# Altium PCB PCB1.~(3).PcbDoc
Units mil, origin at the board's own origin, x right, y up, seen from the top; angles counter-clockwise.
Board outline 6000 x 4000 mil, 2 copper layers (Top Layer, Bottom Layer); 138 components, 71 nets, 353 pads, 0 vias.
Unrouted connection lines stored in the file: 264.
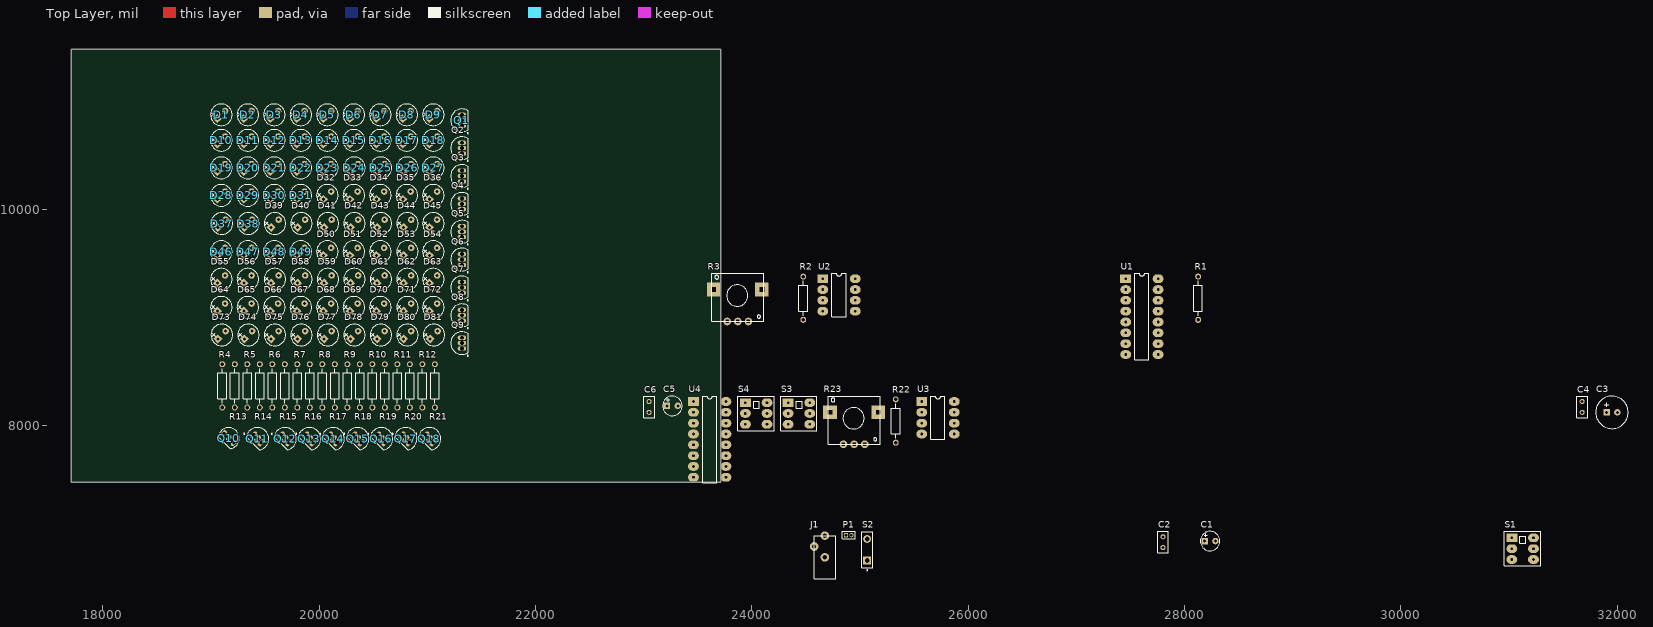
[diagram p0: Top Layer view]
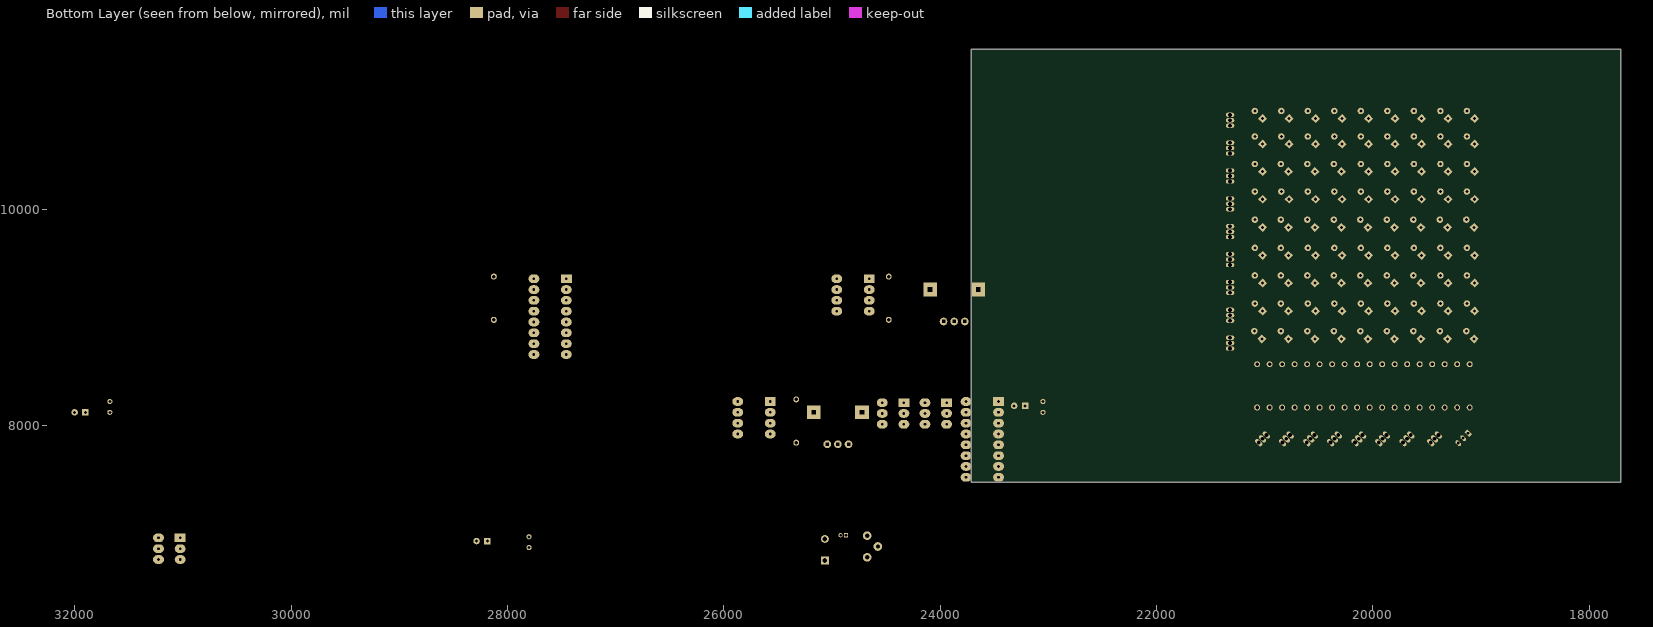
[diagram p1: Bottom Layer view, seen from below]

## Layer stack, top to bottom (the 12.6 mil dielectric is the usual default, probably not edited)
Top Solder: solder mask 0.4, Solder Resist, Dk 3.5
Top Layer: signal copper 1.4
Dielectric 1: dielectric 12.6, FR-4, Dk 4.8
Bottom Layer: signal copper 1.4
Bottom Solder: solder mask 0.4, Solder Resist, Dk 3.5

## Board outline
17710,7480 23710,7480 23710,11480 17710,11480

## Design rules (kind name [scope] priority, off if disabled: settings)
Clearance [All] p1: gap=10
PolygonConnect [All] p1: connectstyle=Relief reliefconductorwidth=10 reliefentries=4 polygonreliefangle="90 Angle" airgapwidth=10
RoutingVias [All] p1: holewidth=28 width=50 viastyle="Through Hole" minholewidth=28 minwidth=50 maxholewidth=28 maxwidth=50
SolderMaskExpansion [All] p1: expansion=4
Width [All] p1: maxlimit=10 minlimit=10 preferedwidth=10
30 further rules are at their usual default settings.

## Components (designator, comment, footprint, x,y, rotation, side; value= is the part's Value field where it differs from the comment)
C1 "Cap Pol2" 1UF电容器 28185,6935 r0 top
C2 "Cap" RAD-0.1 27800,6925 r90 top
C3 "Cap Pol2" 220UF电容 31900,8125 r0 top
C4 "Cap" RAD-0.1 31675,8175 r90 top
C5 "Cap Pol2" 1UF电容器 23215,8185 r0 top
C6 "Cap" RAD-0.1 23050,8175 r90 top
D1 "LED1" 发光二极管 19060,10840 r45 top
D2 "LED1" 发光二极管 19305,10840 r45 top
D3 "LED1" 发光二极管 19550,10840 r45 top
D4 "LED1" 发光二极管 19795,10840 r45 top
D5 "LED1" 发光二极管 20040,10840 r45 top
D6 "LED1" 发光二极管 20285,10840 r45 top
D7 "LED1" 发光二极管 20530,10840 r45 top
D8 "LED1" 发光二极管 20775,10840 r45 top
D9 "LED1" 发光二极管 21020,10840 r45 top
D10 "LED1" 发光二极管 19060,10604.29 r45 top
D11 "LED1" 发光二极管 19305,10604.29 r45 top
D12 "LED1" 发光二极管 19550,10604.29 r45 top
D13 "LED1" 发光二极管 19795,10604.29 r45 top
D14 "LED1" 发光二极管 20040,10604.29 r45 top
D15 "LED1" 发光二极管 20285,10604.29 r45 top
D16 "LED1" 发光二极管 20530,10604.29 r45 top
D17 "LED1" 发光二极管 20775,10604.29 r45 top
D18 "LED1" 发光二极管 21020,10604.29 r45 top
D19 "LED1" 发光二极管 19060,10350 r45 top
D20 "LED1" 发光二极管 19305,10350 r45 top
D21 "LED1" 发光二极管 19550,10350 r45 top
D22 "LED1" 发光二极管 19795,10350 r45 top
D23 "LED1" 发光二极管 20040,10350 r45 top
D24 "LED1" 发光二极管 20290,10350 r45 top
D25 "LED1" 发光二极管 20535,10350 r45 top
D26 "LED1" 发光二极管 20780,10350 r45 top
D27 "LED1" 发光二极管 21020,10350 r45 top
D28 "LED1" 发光二极管 19060,10095 r45 top
D29 "LED1" 发光二极管 19305,10095 r45 top
D30 "LED1" 发光二极管 19550,10095 r45 top
D31 "LED1" 发光二极管 19795,10095 r45 top
D32 "LED1" 发光二极管 20040,10095 r45 top
D33 "LED1" 发光二极管 20285,10095 r45 top
D34 "LED1" 发光二极管 20530,10095 r45 top
D35 "LED1" 发光二极管 20775,10095 r45 top
D36 "LED1" 发光二极管 21020,10095 r45 top
D37 "LED1" 发光二极管 19065,9835 r45 top
D38 "LED1" 发光二极管 19310,9835 r45 top
D39 "LED1" 发光二极管 19555,9835 r45 top
D40 "LED1" 发光二极管 19800,9835 r45 top
D41 "LED1" 发光二极管 20045,9835 r45 top
D42 "LED1" 发光二极管 20290,9835 r45 top
D43 "LED1" 发光二极管 20535,9835 r45 top
D44 "LED1" 发光二极管 20780,9835 r45 top
D45 "LED1" 发光二极管 21020,9835 r45 top
D46 "LED1" 发光二极管 19060,9575 r45 top
D47 "LED1" 发光二极管 19305,9575 r45 top
D48 "LED1" 发光二极管 19550,9575 r45 top
D49 "LED1" 发光二极管 19795,9575 r45 top
D50 "LED1" 发光二极管 20040,9575 r45 top
D51 "LED1" 发光二极管 20285,9575 r45 top
D52 "LED1" 发光二极管 20530,9575 r45 top
D53 "LED1" 发光二极管 20780,9575 r45 top
D54 "LED1" 发光二极管 21020,9575 r45 top
D55 "LED1" 发光二极管 19060,9320 r45 top
D56 "LED1" 发光二极管 19305,9320 r45 top
D57 "LED1" 发光二极管 19555,9320 r45 top
D58 "LED1" 发光二极管 19800,9320 r45 top
D59 "LED1" 发光二极管 20045,9320 r45 top
D60 "LED1" 发光二极管 20290,9320 r45 top
D61 "LED1" 发光二极管 20535,9320 r45 top
D62 "LED1" 发光二极管 20780,9320 r45 top
D63 "LED1" 发光二极管 21020,9320 r45 top
D64 "LED1" 发光二极管 19060,9060 r45 top
D65 "LED1" 发光二极管 19305,9060 r45 top
D66 "LED1" 发光二极管 19550,9060 r45 top
D67 "LED1" 发光二极管 19795,9060 r45 top
D68 "LED1" 发光二极管 20040,9060 r45 top
D69 "LED1" 发光二极管 20285,9060 r45 top
D70 "LED1" 发光二极管 20530,9060 r45 top
D71 "LED1" 发光二极管 20780,9060 r45 top
D72 "LED1" 发光二极管 21020,9060 r45 top
D73 "LED1" 发光二极管 19065,8805 r45 top
D74 "LED1" 发光二极管 19310,8805 r45 top
D75 "LED1" 发光二极管 19555,8805 r45 top
D76 "LED1" 发光二极管 19800,8805 r45 top
D77 "LED1" 发光二极管 20045,8805 r45 top
D78 "LED1" 发光二极管 20290,8805 r45 top
D79 "LED1" 发光二极管 20535,8805 r45 top
D80 "LED1" 发光二极管 20780,8805 r45 top
D81 "LED1" 发光二极管 21025,8805 r45 top
J1 "Phonejack2 TN" ? 24675,6785 r90 top
P1 "MHDR1X2" MHDR1X2 24870,6990 r0 top
Q1 "NPN" TO-226-AA 21320,10825 r0 top
Q2 "NPN" TO-226-AA 21320,10567.5 r0 top
Q3 "NPN" TO-226-AA 21320,10310 r0 top
Q4 "NPN" TO-226-AA 21320,10052.5 r0 top
Q5 "NPN" TO-226-AA 21320,9795 r0 top
Q6 "NPN" TO-226-AA 21320,9537.5 r0 top
Q7 "NPN" TO-226-AA 21320,9280 r0 top
Q8 "NPN" TO-226-AA 21320,9022.5 r0 top
Q9 "NPN" TO-226-AA 21320,8765 r0 top
Q10 "NPN" TO-92-3_L4.9-W3.7-P1.27-L 19164.64,7885.9 r315 top
Q11 "NPN" TO-226-AA 19429.64,7880.36 r225 top
Q12 "NPN" TO-226-AA 19685,7880.36 r225 top
Q13 "NPN" TO-226-AA 19910,7880.36 r225 top
Q14 "NPN" TO-226-AA 20130,7880.36 r225 top
Q15 "NPN" TO-226-AA 20355,7880.36 r225 top
Q16 "NPN" TO-226-AA 20575,7880.36 r225 top
Q17 "NPN" TO-226-AA 20800,7880.36 r225 top
Q18 "NPN" TO-226-AA 21020,7880.36 r225 top
R1 "Res2" AXIAL-0.4 28125,9180 r90 top
R2 "Res2" AXIAL-0.4 24475,9180 r90 top
R3 "RPot" 立式手柄电位器 23870,8965 r0 top
R4 "Res2" AXIAL-0.4 19105,8370 r90 top
R5 "Res2" AXIAL-0.4 19336.18,8370 r90 top
R6 "Res2" AXIAL-0.4 19567.35,8370 r90 top
R7 "Res2" AXIAL-0.4 19798.53,8370 r90 top
R8 "Res2" AXIAL-0.4 20029.71,8370 r90 top
R9 "Res2" AXIAL-0.4 20260.88,8370 r90 top
R10 "Res2" AXIAL-0.4 20492.06,8370 r90 top
R11 "Res2" AXIAL-0.4 20723.23,8370 r90 top
R12 "Res2" AXIAL-0.4 20954.41,8370 r90 top
R13 "Res2" AXIAL-0.4 19220.59,8370 r90 top
R14 "Res2" AXIAL-0.4 19451.76,8370 r90 top
R15 "Res2" AXIAL-0.4 19682.94,8370 r90 top
R16 "Res2" AXIAL-0.4 19914.12,8370 r90 top
R17 "Res2" AXIAL-0.4 20145.29,8370 r90 top
R18 "Res2" AXIAL-0.4 20376.47,8370 r90 top
R19 "Res2" AXIAL-0.4 20607.65,8370 r90 top
R20 "Res2" AXIAL-0.4 20838.82,8370 r90 top
R21 "Res2" AXIAL-0.4 21070,8370 r90 top
R22 "Res2" AXIAL-0.4 25330,8045 r90 top
R23 "RPot" 立式手柄电位器 24945,7830 r0 top
S1 "SW-SPDT" KEY-6 31025,6965 r0 top
S2 "SW-SPST" SPST-2 25065,6855 r90 top
S3 "SW-SPDT" KEY-6 24335,8215 r0 top
S4 "SW-SPDT" KEY-6 23940,8215 r0 top
U1 "CD4017BCN" CD4017 27455,9360 r0 top
U2 "NE555N" NE555 24655,9360 r0 top
U3 "NE555N" NE555 25570,8225 r0 top
U4 "CD4017BCN" CD4017 23460,8225 r0 top

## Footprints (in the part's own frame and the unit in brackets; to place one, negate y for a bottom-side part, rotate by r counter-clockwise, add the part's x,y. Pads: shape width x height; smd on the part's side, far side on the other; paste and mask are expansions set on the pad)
1UF电容器 [mil]
  rect 60x60 hole 28: 1(0,0)
  round 60 hole 28: 2(100,0)
  silkscreen extent -40,-90 140,90
220UF电容 [mil]
  rect 60x60 hole 28: 1(0,0)
  round 60 hole 28: 2(100,0)
  silkscreen extent -100,-150 200,150
AXIAL-0.4 [mm] "Axial Device, Thru-Hole; 2 Leads; 0.4 in Pin Spacing"
  round 1.4 hole 0.85: 1(-5.08,0) 2(5.08,0)
  silkscreen extent -4.06,-1.02 4.06,1.02
CD4017 [mil]
  rect 100x80 hole 25: 1(0,0)
  oval 100x80 hole 25: 2(0,-100) 3(0,-200) 4(0,-300) 5(0,-400) 6(0,-500) 7(0,-600) 8(0,-700) 9(300,-700) 10(300,-600) 11(300,-500) 12(300,-400) 13(300,-300) 14(300,-200) 15(300,-100) 16(300,0)
  silkscreen extent 85,-750 215,50
KEY-6 [mil]
  rect 100x80 hole 25: 1(0,0)
  oval 100x80 hole 25: 2(0,-100) 3(0,-200) 4(200,-200) 5(200,-100) 6(200,0)
  silkscreen extent -70,-260 265,60
MHDR1X2 [mm] "Connector; Header; 2 Position"
  rect 1x1 hole 0.6: 1(0,0)
  round 1 hole 0.6: 2(1.27,0)
  silkscreen extent -0.9,-0.9 2.17,0.9
NE555 [mil]
  rect 100x80 hole 25: 1(0,0)
  oval 100x80 hole 25: 2(0,-100) 3(0,-200) 4(0,-300) 5(300,-300) 6(300,-200) 7(300,-100) 8(300,0)
  silkscreen extent 85,-350 215,50
RAD-0.1 [mm] "Radial Cap, Thru-Hole; 2 Leads; 0.1 in Pin Spacing"
  round 1.2 hole 0.7: 1(-1.27,0) 2(1.27,0)
  silkscreen extent -2.54,-1.27 2.54,1.27
SPST-2 [mm] "Switch; 2 Leads"
  rect 1.85x1.85 hole 1.1: 1(-2.54,0)
  round 1.85 hole 1.1: 2(2.54,0)
  silkscreen extent -4.89,-1.27 4.28,1.27
TO-92-3_L4.9-W3.7-P1.27-L [mm]
  rect 0.9x1.6 hole 0.7: 1(-1.651,0)
  oval 0.9x1.6 hole 0.7: 2(0,0) 3(1.651,0)
  silkscreen extent -2.48,-1.5 2.48,2.48
TO-226-AA [mm] "TO, Flat Index; 3 In-Line, Axial Leads; Body Dia. 4.8mm; Leads 0.55 x 0.51 mm (max)"
  oval 2x1 hole 0.9: 1(0,-1.27) 2(0,0) 3(0,1.27)
  silkscreen extent -2.65,-3.13 1.52,2.65, body extent -2.65,-2.66 1.52,2.66, height 5.33
发光二极管 [mil]
  rect 60x60 hole 28: 1(0,0)
  round 60 hole 28: 2(100,0)
  silkscreen extent -50,-100 150,100
立式手柄电位器 [mm]
  round 1.8 hole 0.7 square: 1(-2.5,0) 2(2.5,0) 3(0,0)
  rect 3.2x3.2 hole 1 square: 4(-5.65,7.5) 5(5.65,7.5)
  silkscreen extent -6.1,0 6.1,11.3
? [mil]
  round 80 hole 40: 1(0,0) 2(100,100) 5(200,0)
  silkscreen extent -200,-100 200,100

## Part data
C1 C3 C5: "Polarized Capacitor (Axial)"
C2 C4 C6: "Capacitor"
D1 D2 D3 D4 D5 D6 D7 D8 D9 D10 D11 D12 D13 D14 D15 D16 D17 D18 D19 D20 D21 D22 D23 D24 D25 D26 D27 D28 D29 D30 D31 D32 D33 D34 D35 D36 D37 D38 D39 D40 D41 D42 D43 D44 D45 D46 D47 D48 D49 D50 D51 D52 D53 D54 D55 D56 D57 D58 D59 D60 D61 D62 D63 D64 D65 D66 D67 D68 D69 D70 D71 D72 D73 D74 D75 D76 D77 D78 D79 D80 D81: "Typical RED GaAs LED"
J1: "Jack Socket, 1/4\" [6.5mm], Thru-Hole, Vertical, 2-Conductor with Tip closed"
P1: "Header, 2-Pin"
Q1 Q2 Q3 Q4 Q5 Q6 Q7 Q8 Q9 Q10 Q11 Q12 Q13 Q14 Q15 Q16 Q17 Q18: "NPN Bipolar Transistor"
R1 R2 R4 R5 R6 R7 R8 R9 R10 R11 R12 R13 R14 R15 R16 R17 R18 R19 R20 R21 R22: "Resistor"
R3 R23: "Potentiometer"
S1 S3 S4: "SPDT Subminiature Toggle Switch, Right Angle Mounting, Vertical Actuation"
S2: "Single-Pole, Single-Throw Switch"
U1 U4: "Decade Counter/Divider with 10 Decoded Outputs"
U2 U3: "General-Purpose Single Bipolar Timer"

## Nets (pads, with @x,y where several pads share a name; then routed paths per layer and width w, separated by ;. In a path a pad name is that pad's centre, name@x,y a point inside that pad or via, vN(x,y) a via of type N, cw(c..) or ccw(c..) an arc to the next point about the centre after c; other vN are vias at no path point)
+5V: C3.1 C4.2 Q1.1 Q2.1 Q3.1 Q4.1 Q5.1 Q6.1 Q7.1 Q8.1 Q9.1 R2.1 R22.1 S2.2 U1.16 U2.4 U2.8 U3.4 U3.8 U4.16
GND: C1.2 C2.2 C3.2 C4.1 C5.2 C6.2 J1.5 P1.1 Q10.3 Q11.3 Q12.3 Q13.3 Q14.3 Q15.3 Q16.3 Q17.3 Q18.3 U1.8 U1.13 U2.1 U3.1 U4.8 U4.13
H1: Q1.2 U1.3
H2: Q2.2 U1.2
H3: Q3.2 U1.4
H4: Q4.2 U1.7
H5: Q5.2 U1.10
H6: Q6.2 U1.1
H7: Q7.2 U1.5
H8: Q8.2 U1.6
H9: Q9.2 U1.9
L1: R13.2 U4.3
L2: R14.2 U4.2
L3: R15.2 U4.4
L4: R16.2 U4.7
L5: R17.2 U4.10
L6: R18.2 U4.1
L7: R19.2 U4.5
L8: R20.2 U4.6
L9: R21.2 U4.9
NetC1_1: C1.1 S1.3
NetC2_1: C2.1 S1.1
NetC5_1: C5.1 S4.3
NetC6_1: C6.1 S4.1
NetD1_1: D1.1 D2.1 D3.1 D4.1 D5.1 D6.1 D7.1 D8.1 D9.1 Q1.3
NetD1_2: D1.2 D10.2 D19.2 D28.2 D37.2 D46.2 D55.2 D64.2 D73.2 R4.2
NetD2_2: D2.2 D11.2 D20.2 D29.2 D38.2 D47.2 D56.2 D65.2 D74.2 R5.2
NetD3_2: D3.2 D12.2 D21.2 D30.2 D39.2 D48.2 D57.2 D66.2 D75.2 R6.2
NetD4_2: D4.2 D13.2 D22.2 D31.2 D40.2 D49.2 D58.2 D67.2 D76.2 R7.2
NetD5_2: D5.2 D14.2 D23.2 D32.2 D41.2 D50.2 D59.2 D68.2 D77.2 R8.2
NetD6_2: D6.2 D15.2 D24.2 D33.2 D42.2 D51.2 D60.2 D69.2 D78.2 R9.2
NetD7_2: D7.2 D16.2 D25.2 D34.2 D43.2 D52.2 D61.2 D70.2 D79.2 R10.2
NetD8_2: D8.2 D17.2 D26.2 D35.2 D44.2 D53.2 D62.2 D71.2 D80.2 R11.2
NetD9_2: D9.2 D18.2 D27.2 D36.2 D45.2 D54.2 D63.2 D72.2 D81.2 R12.2
NetD10_1: D10.1 D11.1 D12.1 D13.1 D14.1 D15.1 D16.1 D17.1 D18.1 Q2.3
NetD19_1: D19.1 D20.1 D21.1 D22.1 D23.1 D24.1 D25.1 D26.1 D27.1 Q3.3
NetD28_1: D28.1 D29.1 D30.1 D31.1 D32.1 D33.1 D34.1 D35.1 D36.1 Q4.3
NetD37_1: D37.1 D38.1 D39.1 D40.1 D41.1 D42.1 D43.1 D44.1 D45.1 Q5.3
NetD46_1: D46.1 D47.1 D48.1 D49.1 D50.1 D51.1 D52.1 D53.1 D54.1 Q6.3
NetD55_1: D55.1 D56.1 D57.1 D58.1 D59.1 D60.1 D61.1 D62.1 D63.1 Q7.3
NetD64_1: D64.1 D65.1 D66.1 D67.1 D68.1 D69.1 D70.1 D71.1 D72.1 Q8.3
NetD73_1: D73.1 D74.1 D75.1 D76.1 D77.1 D78.1 D79.1 D80.1 D81.1 Q9.3
NetJ1_1: J1.1 P1.2 S2.1
NetQ10_1: Q10.1 R4.1
NetQ10_2: Q10.2 R13.1
NetQ11_1: Q11.1 R5.1
NetQ11_2: Q11.2 R14.1
NetQ12_1: Q12.1 R6.1
NetQ12_2: Q12.2 R15.1
NetQ13_1: Q13.1 R7.1
NetQ13_2: Q13.2 R16.1
NetQ14_1: Q14.1 R8.1
NetQ14_2: Q14.2 R17.1
NetQ15_1: Q15.1 R9.1
NetQ15_2: Q15.2 R18.1
NetQ16_1: Q16.1 R10.1
NetQ16_2: Q16.2 R19.1
NetQ17_1: Q17.1 R11.1
NetQ17_2: Q17.2 R20.1
NetQ18_1: Q18.1 R12.1
NetQ18_2: Q18.2 R21.1
NetR1_1: R1.1 U1.15
NetR1_2: R1.2 S3.1 U1.11
NetR2_2: R2.2 R3.2 R3.3 U2.7
NetR3_1: R3.1 S1.2 U2.2 U2.6
NetR22_2: R22.2 R23.2 R23.3 U3.7
NetR23_1: R23.1 S4.2 U3.2 U3.6
NetS3_2: S3.2 U4.14
NetS3_3: S3.3 U3.3
NetU1_14: U1.14 U2.3
NetU4_11: U4.11 U4.15
pads on no net: J1.2 R3.4 R3.5 R23.4 R23.5 S1.4 S1.5 S1.6 S3.4 S3.5 S3.6 S4.4 S4.5 S4.6 U1.12 U2.5 U3.5 U4.12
